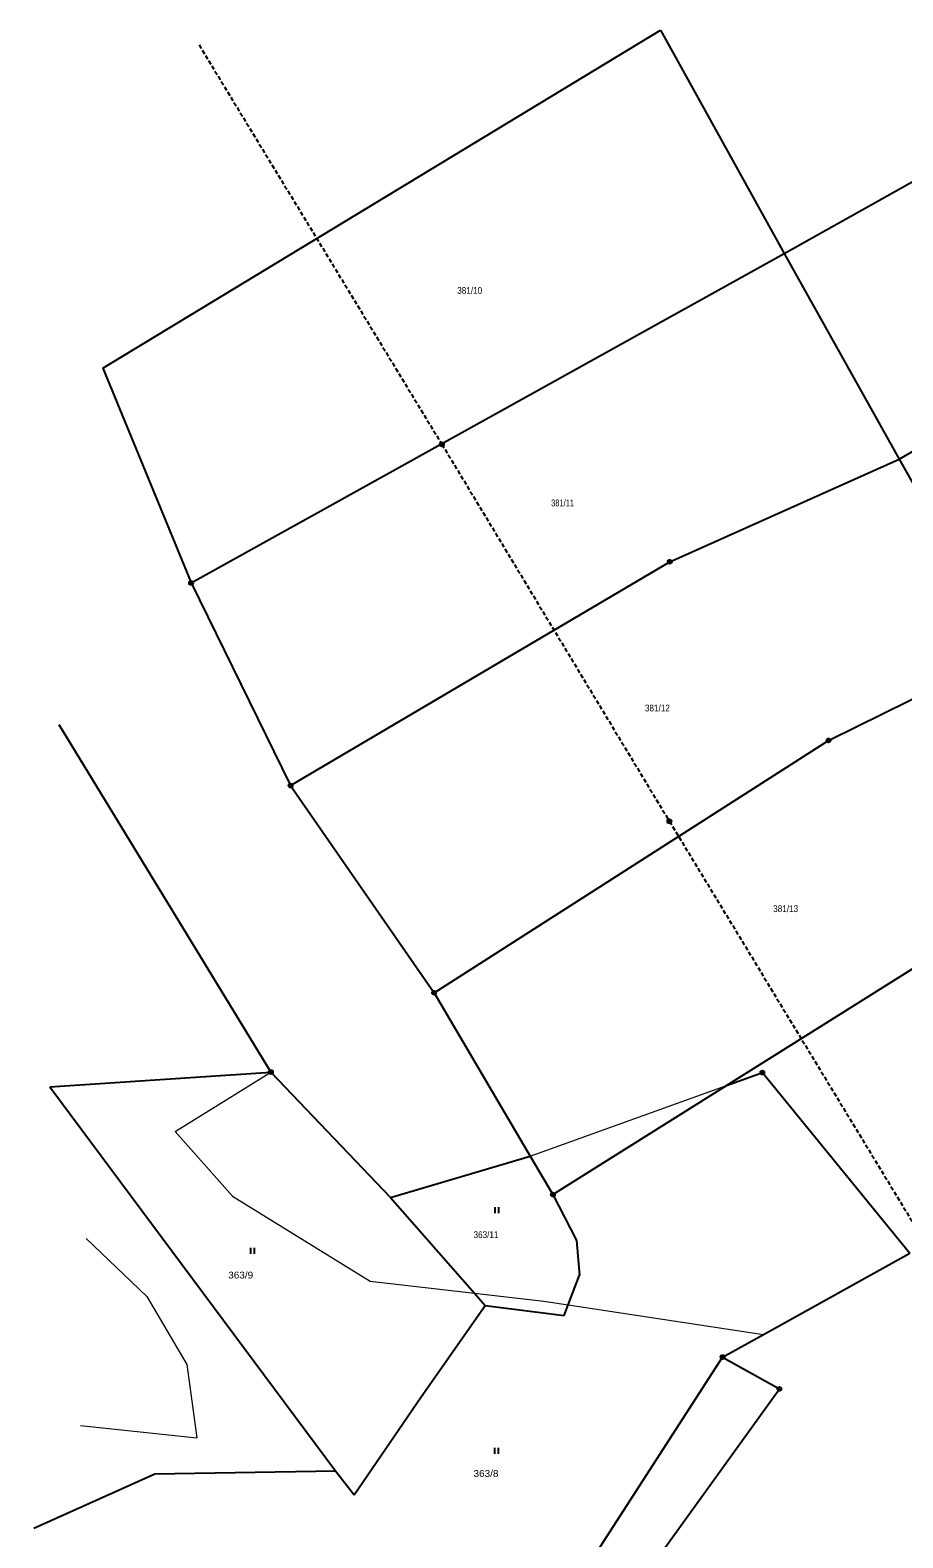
# Model space of a CAD drawing. Extents: x -592965 to -592390, y -1145071 to -1144631.
# Drawn here: x -592878.9 to -592769.5, y -1144835.1 to -1144646.1 of the extents above; entities that cross this region are included whole.
import ezdxf

# ---------------------------------------------------------------- set-up
doc = ezdxf.new("R2010")
doc.units = 0
doc.header["$LTSCALE"] = 0.17
doc.linetypes.add('MEDIUM_DASHED', pattern=[4.5, 3, -1.5])
doc.layers.add('4', color=7, linetype='Continuous', lineweight=25)

msp = doc.modelspace()

# ---------------------------------------------------------------- linework, layer by layer
at = {"layer": '4'}
for p, q in [((-592869.77, -1144688.5), (-592799.86, -1144646.1)), ((-592799.86, -1144646.1), (-592784.33, -1144674.09)), ((-592784.33, -1144674.09), (-592750.58, -1144655.15)), ((-592858.71, -1144715.41), (-592784.33, -1144674.09)), ((-592784.33, -1144674.09), (-592769.91, -1144699.89)), ((-592769.91, -1144699.89), (-592738.34, -1144681.38)), ((-592869.77, -1144688.5), (-592858.71, -1144715.41)), ((-592798.69, -1144712.76), (-592769.91, -1144699.89)), ((-592769.91, -1144699.89), (-592756.36, -1144724.09)), ((-592846.22, -1144740.81), (-592798.69, -1144712.76)), ((-592858.71, -1144715.41), (-592846.22, -1144740.81)), ((-592778.78, -1144735.16), (-592756.36, -1144724.09)), ((-592875.27, -1144733.18), (-592848.69, -1144776.74)), ((-592828.23, -1144766.8), (-592778.78, -1144735.16)), ((-592846.22, -1144740.81), (-592828.23, -1144766.8)), ((-592791.59, -1144778.43), (-592765.88, -1144762.28)), ((-592828.23, -1144766.8), (-592816.17, -1144787.29)), ((-592876.4, -1144778.61), (-592848.69, -1144776.74)), ((-592848.69, -1144776.74), (-592833.71, -1144792.46)), ((-592791.59, -1144778.43), (-592787.07, -1144776.8)), ((-592787.07, -1144776.8), (-592768.57, -1144799.46)), ((-592876.4, -1144778.61), (-592840.59, -1144826.75)), ((-592833.71, -1144792.46), (-592816.17, -1144787.29)), ((-592813.34, -1144792.1), (-592810.38, -1144797.85)), ((-592833.71, -1144792.46), (-592823.17, -1144804.47)), ((-592820.618, -1144793.692), (-592820.618, -1144794.442)), ((-592820.108, -1144794.442), (-592820.108, -1144793.692)), ((-592810.38, -1144797.85), (-592810.01, -1144802.2)), ((-592851.258, -1144798.772), (-592851.258, -1144799.522)), ((-592850.748, -1144799.522), (-592850.748, -1144798.772)), ((-592786.95, -1144809.64), (-592768.57, -1144799.46)), ((-592829.85, -1144817.48), (-592821.83, -1144806)), ((-592792.06, -1144812.47), (-592786.95, -1144809.64)), ((-592815.6, -1144848.96), (-592792.06, -1144812.47)), ((-592792.06, -1144812.47), (-592784.93, -1144816.46)), ((-592800.14, -1144837.58), (-592784.93, -1144816.46)), ((-592838.25, -1144829.75), (-592829.85, -1144817.48)), ((-592820.658, -1144823.862), (-592820.658, -1144824.612)), ((-592820.148, -1144824.612), (-592820.148, -1144823.862)), ((-592878.41, -1144833.93), (-592863.25, -1144827.1)), ((-592863.25, -1144827.1), (-592840.59, -1144826.75)), ((-592840.59, -1144826.75), (-592838.25, -1144829.75))]:
    msp.add_line(p, q, dxfattribs=at)
at = {"layer": '4', "lineweight": 13}
for p, q in [((-592860.68, -1144784.19), (-592848.69, -1144776.74)), ((-592816.17, -1144787.29), (-592791.59, -1144778.43)), ((-592860.68, -1144784.19), (-592853.49, -1144792.29)), ((-592853.49, -1144792.29), (-592843, -1144798.78)), ((-592871.86, -1144797.59), (-592864.26, -1144804.89)), ((-592864.26, -1144804.89), (-592859.24, -1144813.4)), ((-592859.24, -1144813.4), (-592857.99, -1144822.59)), ((-592872.55, -1144821.04), (-592857.99, -1144822.59))]:
    msp.add_line(p, q, dxfattribs=at)
at = {"layer": '4', "linetype": 'MEDIUM_DASHED'}
msp.add_lwpolyline([(-592857.7, -1144647.96), (-592827.25, -1144698.04), (-592798.73, -1144745.3), (-592765.1, -1144800.74), (-592721.92, -1144873.86), (-592693.51, -1144920.47), (-592669.72, -1144961.82), (-592709.34, -1144973.09), (-592761.29, -1144989.89), (-592825.83, -1145034.08), (-592878.88, -1145071.17)], dxfattribs=at)
at = {"layer": '4'}
for points in [[(-592816.17, -1144787.29), (-592813.34, -1144792.1), (-592791.59, -1144778.43)], [(-592811.91, -1144807.28), (-592811.41, -1144805.94), (-592810.01, -1144802.2)], [(-592823.17, -1144804.47), (-592821.83, -1144806), (-592811.91, -1144807.28)]]:
    msp.add_lwpolyline(points, dxfattribs=at)
at = {"layer": '4', "lineweight": 13}
for points in [[(-592843, -1144798.78), (-592836.24, -1144802.96), (-592823.17, -1144804.47), (-592814.49, -1144805.48)], [(-592814.49, -1144805.48), (-592811.41, -1144805.94), (-592786.95, -1144809.64)]]:
    msp.add_lwpolyline(points, dxfattribs=at)
at = {"layer": '4'}
for centre, radius in [((-592827.25, -1144698.04), 0.25), ((-592827.25, -1144698.04), 0.15), ((-592827.25, -1144698.04), 0.075), ((-592798.69, -1144712.76), 0.25), ((-592798.69, -1144712.76), 0.0164), ((-592858.71, -1144715.41), 0.25), ((-592858.71, -1144715.41), 0.0164), ((-592778.78, -1144735.16), 0.25), ((-592778.78, -1144735.16), 0.0164), ((-592846.22, -1144740.81), 0.25), ((-592846.22, -1144740.81), 0.0164), ((-592798.73, -1144745.3), 0.25), ((-592798.73, -1144745.3), 0.15), ((-592798.73, -1144745.3), 0.075), ((-592828.23, -1144766.8), 0.25), ((-592828.23, -1144766.8), 0.0164), ((-592848.69, -1144776.74), 0.25), ((-592848.69, -1144776.74), 0.0164), ((-592787.07, -1144776.8), 0.25), ((-592787.07, -1144776.8), 0.0164), ((-592813.34, -1144792.1), 0.25), ((-592813.34, -1144792.1), 0.0164), ((-592792.06, -1144812.47), 0.25), ((-592792.06, -1144812.47), 0.0164), ((-592784.93, -1144816.46), 0.25), ((-592784.93, -1144816.46), 0.0164)]:
    msp.add_circle(centre, radius, dxfattribs=at)

# ---------------------------------------------------------------- texts
for s, width, p in [('381/10', 0.9, (-592825.33, -1144679.16)), ('381/11', 0.8, (-592813.56, -1144705.8)), ('381/12', 0.9, (-592801.8, -1144731.52)), ('381/13', 0.9, (-592785.72, -1144756.68)), ('363/11', 0.9, (-592823.29, -1144797.55)), ('363/9', 1.1, (-592854.05, -1144802.62)), ('363/8', 1.1, (-592823.29, -1144827.5))]:
    msp.add_text(s, height=0.85, dxfattribs=dict(at, width=width)).set_placement(p)

doc.saveas('drawing.dxf')
